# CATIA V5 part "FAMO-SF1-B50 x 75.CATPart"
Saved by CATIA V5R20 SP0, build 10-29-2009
Part number: FAMO-SF1-B50 x 75
Definition: NONE
Nomenclature: FAMO-SF1-B50 x 75
Source: Unknown
Description: FAMO-SF1-B50 x 75
Bounding box of the stored display mesh (mm): x -13 to 62, y -39.5 to 39.5, z -39.5 to 39.5
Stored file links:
  C:\Users\Utente\Desktop\IO LAVORO\3D X SITO CF\X SITO\FAMO\FAMO-SF1-B50 x 75.CATPart
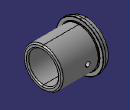
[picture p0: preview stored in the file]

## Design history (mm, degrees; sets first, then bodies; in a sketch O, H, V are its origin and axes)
Body1 "FAMO-SF1-B50 x 75" (main body)
  Solid1: solid without history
